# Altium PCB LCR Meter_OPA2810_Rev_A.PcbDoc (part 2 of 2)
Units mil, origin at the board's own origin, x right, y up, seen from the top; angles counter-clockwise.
Board outline 3760 x 2600 mil, 4 copper layers (L01_TOP, L02_GND, L03_PWR, L04_BOT), stack 62.234 mil thick; 153 components, 56 nets, 334 pads, 170 vias.
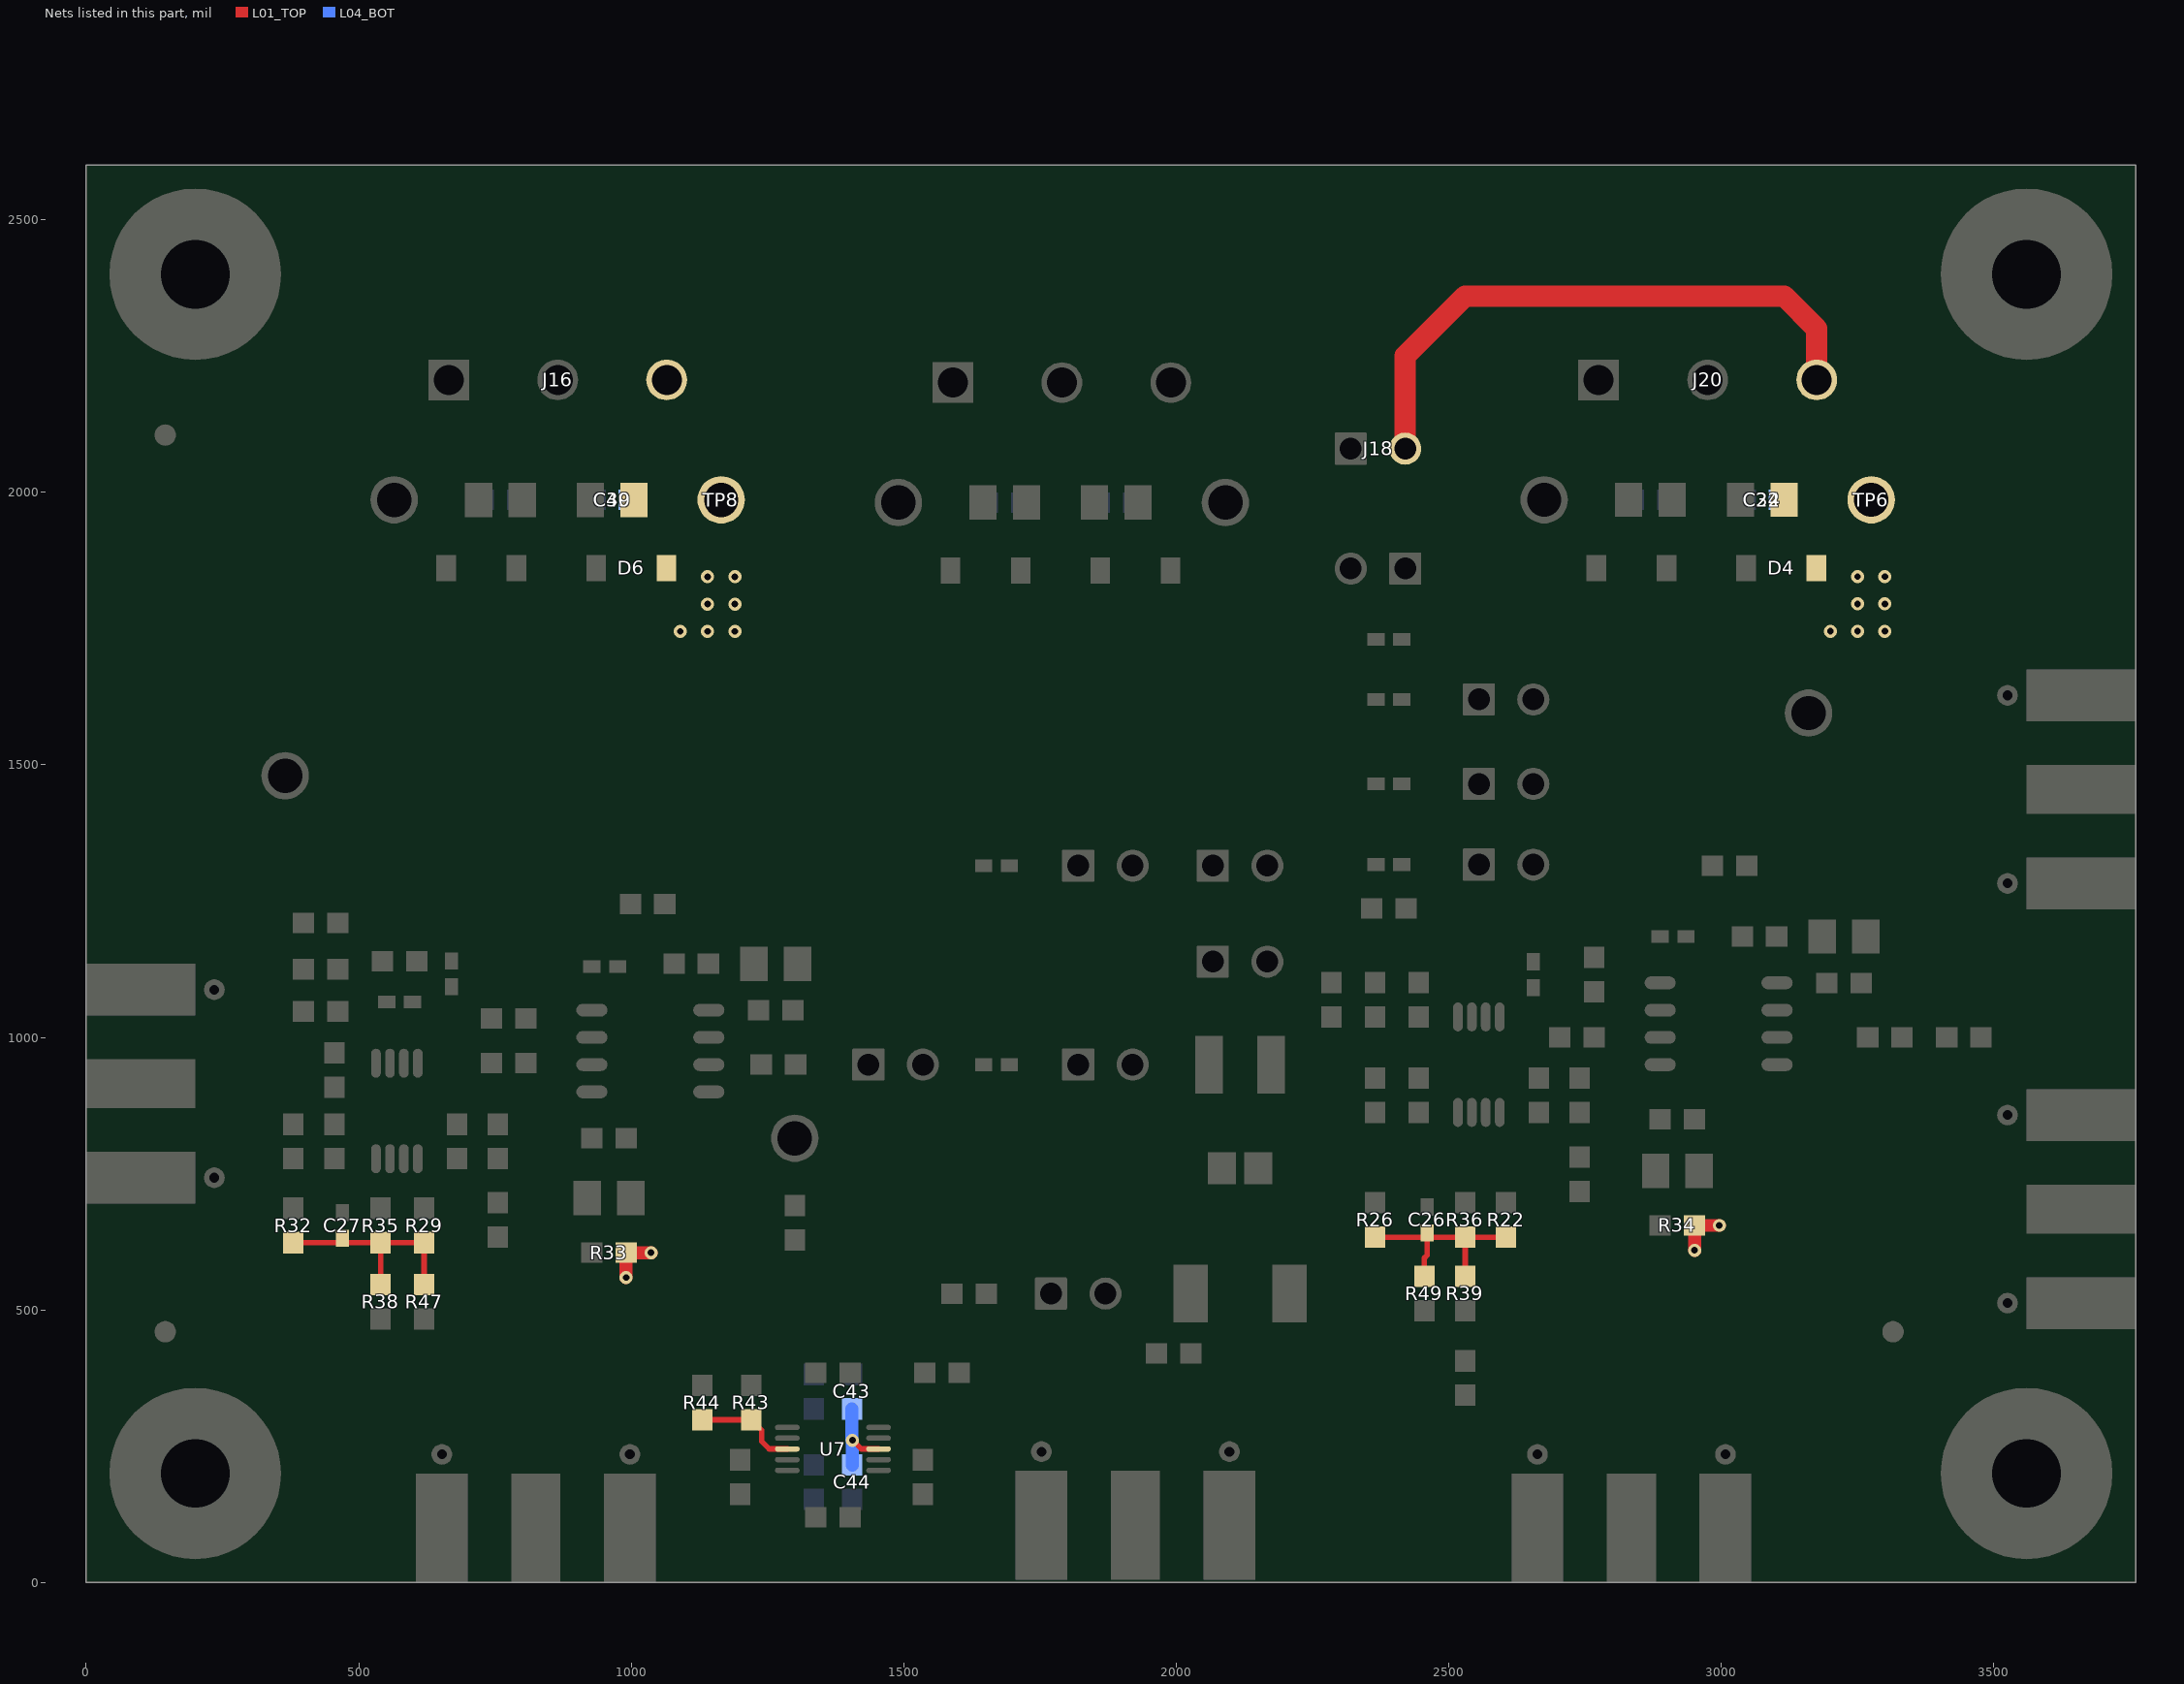
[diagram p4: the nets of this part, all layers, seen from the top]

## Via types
v1: diameter 24, hole 12, L01_TOP to L04_BOT, tented both sides, 170 vias

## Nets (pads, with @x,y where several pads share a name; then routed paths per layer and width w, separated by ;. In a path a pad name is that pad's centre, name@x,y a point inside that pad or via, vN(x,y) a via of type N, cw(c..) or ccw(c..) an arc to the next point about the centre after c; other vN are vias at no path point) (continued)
VEE2: C24.1 C32.2 D4.2 J18.2 J20.3 R33.1 R34.1 TP6.1 | length 1271.2
  L01_TOP w24: v1(990.7,559.5) R33.1@990.7,605 v1(1036.21,605) ; v1(2950.71,609.5) R34.1@2950.71,655.01 v1(2996.22,655.01)
  L01_TOP w39.3: J18.2@2420,2080 2420,2250 2530,2360 3115,2360 3175,2300 J20.3@3175,2206.21
  other v1: 3200,1745.09 3250,1745.09 3300,1745.09 3250,1795.09 3300,1795.09 3250,1845.09 3300,1845.09
VEE3: C39.1 C40.2 C43.1 C44.2 D6.2 J16.3 TP8.1 U7.8 | length 158
  L01_TOP w10: v1(1406,261) 1422,245 U7.8@1453.66,245
  L04_BOT w24: C43.1@1405,318.5 1405,262 v1(1406,261) 1405.43,260.43 C44.2@1405.43,215.47
  other v1: 1090.01,1745 1140.01,1745 1190.01,1745 1140.01,1795 1190.01,1795 1140.01,1845 1190.01,1845
VG: R43.2 R44.1 U7.3 | length 190.5
  L01_TOP w10: R44.1@1130,298.5 R43.2@1220,298.5 1239,279.5 1239,259 1253,245 U7.3@1286.34,245
VIN+: C27.1 R29.2 R32.2 R35.2 R38.1 R47.1 | length 400.5
  L01_TOP w10: R32.2@380,623.5 462.13,623.5 C27.1@470,631.38 477.87,623.5 R35.2@540,623.5 ; R38.1@540,546.5 R35.2@540,623.5 ; R47.1@620,546.5 R29.2@620,623.5 R35.2@540,623.5
VIN-: C26.1 R22.2 R26.2 R36.2 R39.1 R49.1 | length 400.5
  L01_TOP w10: R26.2@2365,633.5 2452.13,633.5 C26.1@2460,641.38 ; R49.1@2455,561.5 2455,595 2460,600 C26.1@2460,641.38 ; R39.1@2530,561.5 R36.2@2530,633.5 ; R22.2@2605,633.5 R36.2@2530,633.5 ; C26.1@2460,641.38 2467.88,633.5 R36.2@2530,633.5
pads on no net: FID1.1 FID2.1 FID3.1 H1.1 H2.1 H3.1 H4.1 H5.0 H6.0 H7.0 H8.0 LBL1.0 U3.2 U3.5 U3.8 U4.2 U4.5 U4.8

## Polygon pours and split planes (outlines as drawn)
GND on L01_TOP "L01_TOP_GND_P016" (solid, remove dead copper, pour order 16): 765,1740 780,1725 945,1725 960,1740 960,1930 950,1940 950,2250 930,2270 795,2270 775,2250 775,1940 765,1930
VCC3 on L01_TOP "L01_TOP_VCC3_P020" (solid, remove dead copper, pour order 20): 490,1755 520,1725 655,1725 685,1755 685,1885 745,1945 745,2030 735,2040 735,2250 715,2270 520,2270 490,2240
VEE3 on L01_TOP "L01_TOP_VEE3_P024" (solid, remove dead copper, pour order 24): 1045.01,1739.99 1060,1725 1225,1725 1240.01,1740.01 1240.01,2240 1210.01,2270 1015.01,2270 995.01,2250 995.01,2040 985.01,2030 985.01,1945 1045.01,1885
VEE1 on L01_TOP "L01_TOP_VEE1_P028" (solid, remove dead copper, pour order 28): 1970.01,1734.99 1985,1720 2150,1720 2165.01,1735.01 2165.01,2235 2135.01,2265 1940.01,2265 1920.01,2245 1920.01,2035 1910.01,2025 1910.01,1940 1970.01,1880
VCC1 on L01_TOP "L01_TOP_VCC1_P030" (solid, remove dead copper, pour order 30): 1415,1750 1445,1720 1580,1720 1610,1750 1610,1880 1670,1940 1670,2025 1660,2035 1660,2245 1640,2265 1445,2265 1415,2235
GND on L01_TOP "L01_TOP_GND_P032" (solid, remove dead copper, pour order 32): 1690,1735 1705,1720 1870,1720 1885,1735 1885,1925 1875,1935 1875,2245 1855,2265 1720,2265 1700,2245 1700,1935 1690,1925
VEE2 on L01_TOP "L01_TOP_VEE2_P040" (solid, remove dead copper, pour order 40): 3155,1740.08 3170,1725.09 3335,1725.09 3350,1740.1 3350,2240.09 3320,2270.09 3125,2270.09 3105,2250.09 3105,2040.09 3095,2030.09 3095,1945.09 3155,1885.09
VCC2 on L01_TOP "L01_TOP_VCC2_P042" (solid, remove dead copper, pour order 42): 2600,1755.09 2630,1725.09 2765,1725.09 2795,1755.09 2795,1885.09 2855,1945.09 2855,2030.09 2845,2040.09 2845,2250.09 2825,2270.09 2630,2270.09 2600,2240.09
GND on L01_TOP "L01_TOP_GND_P044" (solid, remove dead copper, pour order 44): 2875,1740.09 2890,1725.09 3055,1725.09 3070,1740.09 3070,1930.09 3060,1940.09 3060,2250.09 3040,2270.09 2905,2270.09 2885,2250.09 2885,1940.09 2875,1930.09
GND on L01_TOP "L01_TOP_GND_P052" (solid, remove dead copper, pour order 52): 0,2600 0,0 3760,0 3760,2600
GND on L04_BOT "L04_BOT_GND_P018" (solid, remove dead copper, pour order 18): 765,1740 780,1725 945,1725 960,1740 960,1930 950,1940 950,2250 930,2270 795,2270 775,2250 775,1940 765,1930
VCC3 on L04_BOT "L04_BOT_VCC3_P022" (solid, remove dead copper, pour order 22): 490,1755 520,1725 655,1725 685,1755 685,1885 745,1945 745,2030 735,2040 735,2250 715,2270 520,2270 490,2240
VEE3 on L04_BOT "L04_BOT_VEE3_P026" (solid, remove dead copper, pour order 26): 1045.01,1739.99 1060,1725 1225,1725 1240.01,1740.01 1240.01,2240 1210.01,2270 1015.01,2270 995.01,2250 995.01,2040 985.01,2030 985.01,1945 1045.01,1885
VEE1 on L04_BOT "L04_BOT_VEE1_P034" (solid, remove dead copper, pour order 34): 1970.01,1734.99 1985,1720 2150,1720 2165.01,1735.01 2165.01,2235 2135.01,2265 1940.01,2265 1920.01,2245 1920.01,2035 1910.01,2025 1910.01,1940 1970.01,1880
VCC1 on L04_BOT "L04_BOT_VCC1_P036" (solid, remove dead copper, pour order 36): 1415,1750 1445,1720 1580,1720 1610,1750 1610,1880 1670,1940 1670,2025 1660,2035 1660,2245 1640,2265 1445,2265 1415,2235
GND on L04_BOT "L04_BOT_GND_P038" (solid, remove dead copper, pour order 38): 1690,1735 1705,1720 1870,1720 1885,1735 1885,1925 1875,1935 1875,2245 1855,2265 1720,2265 1700,2245 1700,1935 1690,1925
VEE2 on L04_BOT "L04_BOT_VEE2_P046" (solid, remove dead copper, pour order 46): 3155,1740.08 3170,1725.09 3335,1725.09 3350,1740.1 3350,2240.09 3320,2270.09 3125,2270.09 3105,2250.09 3105,2040.09 3095,2030.09 3095,1945.09 3155,1885.09
VCC2 on L04_BOT "L04_BOT_VCC2_P048" (solid, remove dead copper, pour order 48): 2600,1755.09 2630,1725.09 2765,1725.09 2795,1755.09 2795,1885.09 2855,1945.09 2855,2030.09 2845,2040.09 2845,2250.09 2825,2270.09 2630,2270.09 2600,2240.09
GND on L04_BOT "L04_BOT_GND_P050" (solid, remove dead copper, pour order 50): 2875,1740.09 2890,1725.09 3055,1725.09 3070,1740.09 3070,1930.09 3060,1940.09 3060,2250.09 3040,2270.09 2905,2270.09 2885,2250.09 2885,1940.09 2875,1930.09
GND on L04_BOT "L04_BOT_GND_P054" (solid, remove dead copper, pour order 54): 0,2600 0,0 3760,0 3760,2600
GND on L02_GND (split plane): 3739.9,20.1 20.1,20.1 20.1,2579.9 3739.9,2579.9
VCC2 on L03_PWR (split plane): 3083.44,1029.56 2867.56,1029.56 2867.56,1287 3007,1287 3007,1342 3006,1343 2867.56,1343 2867.56,1689 2867.32,1691.45 2866.6,1693.81 2865.44,1695.98 2863.88,1697.88 2861.98,1699.44 2859.81,1700.6 2857.45,1701.32 2855,1701.56 2607.56,1701.56 2607.56,2370 2607.32,2372.45 2606.6,2374.81 2605.44,2376.98 2603.88,2378.88 2601.98,2380.44 2599.81,2381.6 2597.45,2382.32 2595,2382.56 1412,2382.56 1409.55,2382.32 1407.19,2381.6 1405.02,2380.44 1403.12,2378.88 1401.56,2376.98 1400.4,2374.81 1399.68,2372.45 1399.44,2370 1399.44,1095.56 973.56,1095.56 973.56,1173.44 1045,1173.44 1047.45,1173.68 1049.81,1174.4 1051.98,1175.56 1053.88,1177.12 1055.44,1179.02 1056.6,1181.19 1057.32,1183.55 1057.56,1186 1057.56,1362.44 1257,1362.44 1259.45,1362.68 1261.81,1363.4 1263.98,1364.56 1265.88,1366.12 1267.44,1368.02 1268.6,1370.19 1269.32,1372.55 1269.56,1375 1269.56,2579.9 3083.44,2579.9
GND on L03_PWR (split plane): 2292,901 2312.44,901 2312.44,724.98 2208.2,724.98 2208.2,933 2260,933
VEE2 on L03_PWR (split plane): 3739.9,20.1 1609.56,20.1 1609.56,563 1609.32,565.45 1608.6,567.81 1607.44,569.98 1605.88,571.88 1603.98,573.44 1601.81,574.6 1599.45,575.32 1597,575.56 1175.02,575.56 1172.57,575.32 1170.21,574.6 1168.04,573.44 1166.14,571.88 1019.82,425.56 955.56,425.56 955.56,670.44 1960.44,670.44 1960.44,229 1960.68,226.55 1961.4,224.19 1962.56,222.02 1964.12,220.12 1966.02,218.56 1968.19,217.4 1970.55,216.68 1973,216.44 2855,216.44 2857.45,216.68 2859.81,217.4 2861.98,218.56 2863.88,220.12 2865.44,222.02 2866.6,224.19 2867.32,226.55 2867.56,229 2867.56,980 2918,980 2924,986 2924,1004.44 3067,1004.44 3067,988 3075.01,979.99 3249,979.99 3260,968.99 3294.01,968.99 3294.01,1028.99 3264,1028.99 3255,1019.99 3108.56,1019.99 3108.56,2579.9 3739.9,2579.9
VCC1 on L03_PWR (split plane): 179 vertices, not listed, extent 594.56,241.56 2842.44,2357.44
VEE1 on L03_PWR (split plane): 2312.44,1337.48 2279.49,1337.48 2279.49,1300.51 2280,1300 2312.44,1300 2312.44,944 2301,944 2274,971 2208.2,971 2208.2,1299.8 2259,1299.98 2259,1337.48 2216.98,1337.48 2216.98,1364.98 2125,1364.98 2125,594.96 2164.99,594.96 2164.99,465.04 2251.6,465.04 2251.6,674 2312.44,674 2312.44,241.56 1985.56,241.56 1985.56,683 1985.32,685.45 1984.6,687.81 1983.44,689.98 1981.88,691.88 1979.98,693.44 1977.81,694.6 1975.45,695.32 1973,695.56 943,695.56 940.55,695.32 938.19,694.6 936.02,693.44 934.12,691.88 932.56,689.98 931.4,687.81 930.68,685.45 930.44,683 930.44,425.56 566.2,425.56 309.56,682.2 309.56,866 309.56,1362.44 569.44,1362.44 569.44,1166 516,1166 516,1040 569.44,986.56 569.44,984 511,984 511,745 546,745 546,715 450,715 450,658 568,658 568,745 569.44,745 569.44,565 569.68,562.55 570.4,560.19 571.56,558.02 573.12,556.12 575.02,554.56 577.19,553.4 579.55,552.68 582,552.44 807,552.44 809.45,552.68 811.81,553.4 813.98,554.56 815.88,556.12 817.44,558.02 818.6,560.19 819.32,562.55 819.56,565 819.56,816.44 1784,816.44 1786.45,816.68 1788.81,817.4 1790.98,818.56 1792.88,820.12 1794.44,822.02 1795.6,824.19 1796.32,826.55 1796.56,829 1796.56,1965.44 2312.44,1965.44
VEE3 on L03_PWR (split plane): 1244.44,1387.56 297,1387.56 294.55,1387.32 292.19,1386.6 290.02,1385.44 288.12,1383.88 286.56,1381.98 285.4,1379.81 284.68,1377.45 284.44,1375 284.44,866 284.44,677 284.68,674.55 285.4,672.19 286.56,670.02 288.12,668.12 552.12,404.12 554.02,402.56 556.19,401.4 558.55,400.68 561,400.44 1025.02,400.44 1027.47,400.68 1029.82,401.4 1032,402.56 1033.9,404.12 1180.22,550.44 1584.44,550.44 1584.44,20.1 1366.56,20.1 1366.56,408 1366.32,410.45 1365.6,412.81 1364.44,414.98 1362.88,416.88 1360.98,418.44 1358.81,419.6 1356.45,420.32 1354,420.56 1184,420.56 1181.55,420.32 1179.19,419.6 1177.02,418.44 1175.12,416.88 1173.56,414.98 1172.4,412.81 1171.68,410.45 1171.44,408 1171.44,234.56 320.56,234.56 320.56,327 320.32,329.45 319.6,331.81 318.44,333.98 316.88,335.88 314.98,337.44 312.81,338.6 310.45,339.32 308,339.56 151.56,339.56 151.56,1606.44 867,1606.44 869.45,1606.68 871.81,1607.4 873.98,1608.56 875.88,1610.12 877.44,1612.02 878.6,1614.19 879.32,1616.55 879.56,1619 879.56,2579.9 1244.44,2579.9
VCC3 on L03_PWR (split plane): 854.44,1631.56 139,1631.56 136.55,1631.32 134.19,1630.6 132.02,1629.44 130.12,1627.88 128.56,1625.98 127.4,1623.81 126.68,1621.45 126.44,1619 126.44,327 126.68,324.55 127.4,322.19 128.56,320.02 130.12,318.12 132.02,316.56 134.19,315.4 136.55,314.68 139,314.44 295.44,314.44 295.44,222 295.68,219.55 296.4,217.19 297.56,215.02 299.12,213.12 301.02,211.56 303.19,210.4 305.55,209.68 308,209.44 1184,209.44 1186.45,209.68 1188.81,210.4 1190.98,211.56 1192.88,213.12 1194.44,215.02 1195.6,217.19 1196.32,219.55 1196.56,222 1196.56,395.44 1310.02,395.44 1310.02,377.02 1274,341 1274,293 1259,293 1259,277 1312,277 1312,295 1300,295 1300,327 1330,357 1341.44,357 1341.44,208.56 1337,213 1259,213 1259,198 1310,198 1327,181 1327,146 1310,146 1310,93 1341.44,93 1341.44,20.1 20.1,20.1 20.1,2579.9 854.44,2579.9

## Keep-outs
Keep-Out Layer:
  text ".Layer_Name" at 577,-858.49 h60

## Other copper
L01_TOP:
  text ".Layer_Name" at 577,-858.49 h60
L04_BOT:
  text ".Layer_Name" at 577,-858.49 h60
L02_GND (plane layer: these items are gaps in the copper):
  region: 2125,594.96 2164.99,594.96 2164.99,465.04 2251.6,465.04 2251.6,674 2392.27,674 2392.27,724.98 2208.2,724.98 2208.2,933 2260,933 2292,901 2388,901 2392.27,905.27 2392.27,927.9 2418.25,953.88 2496,953.88 2496,830 2614,830 2614,1024 2656,1024 2674,1006 2674,973 2727,973 2727,1020 2692,1055 2692,1068 2726,1102 2726,1210 2803,1287 3007,1287 3007,1342 3006,1343 2799,1343 2692,1236 2692,1120 2682,1110 2634,1110 2634,1052 2614,1052 2614,1069 2608,1069 2608,1071 2583,1071 2583,1069 2578,1069 2578,1071 2557,1071 2557,1069 2496,1069 2496,985 2398,985 2375,962 2344,962 2326,944 2301,944 2274,971 2208.2,971 2208.2,1299.8 2208,1300 2321,1300 2321,1202 2381,1202 2381,1760 2342,1760 2342,1337.48 2216.98,1337.48 2216.98,1364.98 2125,1364.98
  region: 880,1217 1022,1217 1022,1273 861,1273 701,1113 648,1113 648,1060 599,1011 594,1011 570,1035 570,1166 516,1166 516,1040 572,984 511,984 511,745 546,745 546,715 450,715 450,658 568,658 568,745 572,745 572,658 647.27,658 647.27,715 594,715 594,745 629,745 629,921 766,921 766,980 629,980 629,984 625,984 625,989 710,1074 737,1074
  region: 783,921 836,921 845,930 958,930 964,936 964,961 955,970 851,970 840,981 840,1064 836,1068 783,1068
  region: 1379,357 1483,357 1483,277 1478,272 1427,272 1427,257 1497,257 1510,270 1510,358 1562,358 1562,412 1379,412
  region: 1312,277 1259,277 1259,293 1274,293 1274,341 1310.02,377.02 1310.02,412.2 1360.05,412.2 1362.27,409.98 1362.27,357.73 1363,357 1330,357 1300,327 1300,295 1312,295
  region: 1259,213 1337,213 1361,189 1361,93 1310,93 1310,146 1327,146 1327,181 1310,198 1259,198
  region: 1481,213 1403,213 1379,189 1379,93 1430,93 1430,146 1413,146 1413,181 1430,198 1481,198
  region: 1229.99,918.99 1264,918.99 1264,978.99 1233.99,978.99 1224.99,969.99 1111.99,969.99 1105.99,963.99 1105.99,938.99 1114.99,929.99 1218.99,929.99
  region: 2739,971 2796,971 2805,980 2918,980 2924,986 2924,1011 2915,1020 2811,1020 2794,1037.01 2794,1118 2739,1118
  region: 3074.99,1019.99 3067,1012 3067,988 3075.01,979.99 3249,979.99 3260,968.99 3294.01,968.99 3294.01,1028.99 3264,1028.99 3255,1019.99
  text ".Layer_Name" at 577,-858.49 h60
L03_PWR (plane layer: these items are gaps in the copper):
  region: 2557,782.5 2578,761.5 2578,672 2632.27,672 2632.27,756.73 2579,810 2579,830 2614,830 2614,1024 2656,1024 2674,1006 2674,973 2727,973 2727,1020 2692,1055 2692,1068 2726,1102 2726,1210 2803,1287 3007,1287 3007,1342 3006,1343 2799,1343 2692,1236 2692,1120 2682,1110 2634,1110 2634,1052 2614,1052 2614,1069 2608,1069 2608,1071 2583,1071 2583,1069 2578,1069 2578,1071 2557,1071 2557,1069 2496,1069 2496,985 2456,985 2456,953.88 2496,953.88 2496,830 2531,830 2531,804 2502,775 2502,715 2439,715 2439,670 2553,670 2553,830 2557,830
  region: 880,1217 1022,1217 1022,1273 861,1273 701,1113 648,1113 648,1060 599,1011 594,1011 570,1035 570,1166 516,1166 516,1040 572,984 511,984 511,745 546,745 546,715 450,715 450,658 568,658 568,745 572,745 572,658 647.27,658 647.27,715 594,715 594,745 629,745 629,921 766,921 766,980 629,980 629,984 625,984 625,989 710,1074 737,1074
  region: 783,921 836,921 845,930 958,930 964,936 964,961 955,970 851,970 840,981 840,1064 836,1068 783,1068
  region: 1229.99,918.99 1264,918.99 1264,978.99 1233.99,978.99 1224.99,969.99 1111.99,969.99 1105.99,963.99 1105.99,938.99 1114.99,929.99 1218.99,929.99
  region: 1312,277 1259,277 1259,293 1274,293 1274,341 1310.02,377.02 1310.02,412.2 1360.05,412.2 1362.27,409.98 1362.27,357.73 1363,357 1330,357 1300,327 1300,295 1312,295
  region: 1379,357 1483,357 1483,277 1478,272 1427,272 1427,257 1497,257 1510,270 1510,358 1562,358 1562,412 1379,412
  region: 1259,213 1337,213 1361,189 1361,93 1310,93 1310,146 1327,146 1327,181 1310,198 1259,198
  region: 1481,213 1403,213 1379,189 1379,93 1430,93 1430,146 1413,146 1413,181 1430,198 1481,198
  region: 2432,953.88 2432,985 2398,985 2375,962 2344,962 2326,944 2301,944 2274,971 2208.2,971 2208.2,1299.8 2259,1299.98 2259,1337.48 2216.98,1337.48 2216.98,1364.98 2125,1364.98 2125,594.96 2164.99,594.96 2164.99,465.04 2251.6,465.04 2251.6,674 2392.27,674 2392.27,724.98 2208.2,724.98 2208.2,933 2260,933 2292,901 2388,901 2392.27,905.27 2392.27,927.9 2418.25,953.88
  region: 2739,971 2796,971 2805,980 2918,980 2924,986 2924,1011 2915,1020 2811,1020 2794,1037.01 2794,1118 2739,1118
  region: 3074.99,1019.99 3067,1012 3067,988 3075.01,979.99 3249,979.99 3260,968.99 3294.01,968.99 3294.01,1028.99 3264,1028.99 3255,1019.99
  region: 2279.49,1337.48 2279.49,1300.51 2280,1300 2321,1300 2321,1202 2381,1202 2381,1760 2336.12,1760 2336.12,1337.48
  lines w25: 582,1375 582,565 807,565 807,829 1784,829 1784,1978 2325,1978 2325,229 2324,229 ; 867,2780 867,1619 139,1619 139,327 308,327 308,222 1184,222 1184,408 1354,408 1354,-70 ; 943,413 943,683 1973,683 1973,229 2855,229 2855,1017 ; 1045,1375 1045,1186 961,1186 961,1083 1412,1083 1412,2370 2595,2370 2595,1689 2855,1689 2855,1017 ; 1257,2784 1257,1375 297,1375 297,866 297,677 561,413 1025.02,413 1175.02,563 1597,563 1597,-67 ; 3096,2681 3096,1017 2855,1017
  text ".Layer_Name" at 577,-858.49 h60
Multi-Layer:
  pour cut-out: 511,984 629,984 629,745 511,745
  pour cut-out: 2496,1069 2614,1069 2614,830 2496,830
  pour cut-out: 511,984 629,984 629,745 511,745
  pour cut-out: 572,921 572,984 516,1040 516,1166 570,1166 570,1035 594,1011 594,921
  pour cut-out: 766,921 766,980 628,980 625,983 625,989 710,1074 737,1074 880,1217 1022,1217 1022,1273 861,1273 701,1113 648,1113 648,1060 598,1010 598,921
  pour cut-out: 783,921 836,921 845,930 958,930 964,936 964,961 955,970 851,970 840,981 840,1064 836,1068 783,1068
  pour cut-out: 1229.99,918.99 1264,918.99 1264,978.99 1233.99,978.99 1224.99,969.99 1111.99,969.99 1105.99,963.99 1105.99,938.99 1114.99,929.99 1218.99,929.99
  pour cut-out: 568,808 568,658 450,658 450,715 546,715 546,808
  pour cut-out: 572,808 572,658 647.27,658 647.27,715 594,715 594,808
  pour cut-out: 2557,1071 2557,1005 2537,985 2398,985 2375,962 2344,962 2326,944 2301,944 2274,971 2208.2,971 2208.2,1299.8 2208,1300 2321,1300 2321,1202 2381,1202 2381,1760 2342,1760 2342,1337.48 2216.98,1337.48 2216.98,1364.98 2125,1364.98 2125,594.96 2164.99,594.96 2164.99,465.04 2251.6,465.04 2251.6,674 2392.27,674 2392.27,724.98 2208.2,724.98 2208.2,933 2260,933 2292,901 2388,901 2392.27,905.27 2392.27,927.9 2418.25,953.88 2546.88,953.88 2578,985 2578,1071
  pour cut-out: 2583,1071 2583,1006 2608,1006 2608,1024 2656,1024 2674,1006 2674,973 2727,973 2727,1020 2692,1055 2692,1068 2726,1102 2726,1210 2803,1287 3007,1287 3007,1342 3006,1343 2799,1343 2692,1236 2692,1120 2682,1110 2634,1110 2634,1052 2608,1052 2608,1071
  pour cut-out: 2739,971 2796,971 2805,980 2918,980 2924,986 2924,1011 2915,1020 2811,1020 2794,1037.01 2794,1118 2739,1118
  pour cut-out: 3074.99,1019.99 3067,1012 3067,988 3075.01,979.99 3249,979.99 3260,968.99 3294.01,968.99 3294.01,1028.99 3264,1028.99 3255,1019.99
  pour cut-out: 2579,810 2632.27,756.73 2632.27,672 2578,672 2578,761.5 2557,782.5 2557,893 2579,893
  pour cut-out: 2502,715 2502,775 2531,804 2531,893 2553,893 2553,670 2439,670 2439,715
  pour cut-out: 1312,277 1259,277 1259,293 1274,293 1274,341 1310.02,377.02 1310.02,412.2 1360.05,412.2 1362.27,409.98 1362.27,357.73 1363,357 1330,357 1300,327 1300,295 1312,295
  pour cut-out: 1379,357 1483,357 1483,277 1478,272 1427,272 1427,257 1497,257 1510,270 1510,358 1562,358 1562,412 1379,412
  pour cut-out: 1481,213 1403,213 1379,189 1379,93 1430,93 1430,146 1413,146 1413,181 1430,198 1481,198
  pour cut-out: 1259,213 1337,213 1361,189 1361,93 1310,93 1310,146 1327,146 1327,181 1310,198 1259,198

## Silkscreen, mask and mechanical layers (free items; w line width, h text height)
Top Overlay:
  region: 1485,2375 1185,2375 1185,2275 1485,2275
  lines w7: 385,895 400,895 420,875 ; 430,585 430,595 440,605 ; 488,561 488,578 502,592 ; 520,1180 520,1240 530,1250
  text "VEE3" at 1295,1905 h72.83 r90
  text "VEE1" at 2225,1905 h72.83 r90
  text "VEE2" at 3420,1905 h72.83 r90
  text "VCC1" at 1405,1900 h72.83 r90
  text "VCC3" at 480,1895 h72.83 r90
  text "VCC2" at 2585,1895 h72.83 r90
  text "NOV 2018" at 3650,1805 h72.83 r90
  text "4 LAYER" at 3720,1805 h72.83 r90
  text "GND" at 3085,1465 h72.83
  text "GND" at 285,1345 h72.83
  text "V1_OUT" at 3460,1220 h72.83 r90
  text "IN_TP" at 1355,705 h72.83
  text "INPUT" at 75,605 h72.83
  text "V2_OUT" at 3210,595 h72.83
  text "'.PRJ_Number'.PCB_Rev" at 2590,340 h80
  text "V3_OUT" at 715,310 h72.83
  text "VCA_OUT" at 1840,305 h72.83
  text "V4_OUT" at 2330,175 h72.83
  text ".Layer_Name" at 577,-858.49 h60
Bottom Overlay:
  text ".Layer_Name" at 577,-858.49 h60
Top Paste:
  text ".Layer_Name" at 577,-858.49 h60
Bottom Paste:
  text ".Layer_Name" at 577,-858.49 h60
Top Solder:
  text ".Layer_Name" at 577,-858.49 h60
  text ".Layer_Name" at 577,-858.49 h60
Bottom Solder:
  text ".Layer_Name" at 577,-858.49 h60
Drill Guide:
  text ".Layer_Name" at 577,-858.49 h60
M1 Board Outline:
  the board outline again, w10
  text ".Layer_Name" at 2870,-130 h60
M2 Board Dimensions:
  rectangle: 125,-400 500,-275
  rectangle: 0,-275 125,-150
  lines w7: 0,-275 1000,-275 ; 125,-400 125,-150 ; 250,-400 250,-150 ; 500,-400 500,-150 ; 750,-400 750,-150 ; 0,-400 0,-150 1000,-150 1000,-400 0,-400
  text ".Layer_Name" at 577,-858.49 h60
M3 3D STEP Top:
  text ".Layer_Name" at 577,-858.49 h60
M4 3D STEP Bottom:
  text ".Layer_Name" at 577,-858.49 h60
M5 Assembly Top:
  lines w10: -292,-930.17 6308,-930.17 ; -292,-726.83 6310,-726.83 ; -292,-523.5 -292,-1133.5 3713,-1133.5 6310,-1133.5 6310,-523.5 -291.5,-523.5 -291.5,-1133.5 1284,-1133.5 ; 2173,-1133.5 2173,-523.5 ; 3440,-726.83 3440,-523.5 ; 4280,-726.83 4280,-523.5 ; 4902,-1140 4902,-937.17
  text "COMPONENTS MARKED 'DNP' SHOULD NOT BE POPULATED." at 1153.5,-318.5 h60
  text "ASSEMBLY VARIANT:" at 1153,-434 h60
  text ".VariantName" at 2189,-434 h60
  text "PCB VIEWED FROM TOP SIDE" at -228.5,-655.67 h60
  text "BOARD #:" at 2248,-655.67 h60
  text ".PRJ_Number" at 2793.5,-655.67 h60
  text "REV:" at 3638,-655.67 h60
  text ".PCB_Rev" at 3929.5,-655.67 h60
  text "SVN REV:" at 4476,-655.67 h60
  text ".VersionControl_RevNumber" at 4982,-655.67 h60
  text "TID #:" at 2248,-859 h60
  text ".TID" at 2793.5,-859 h60
  text "PLOT NAME =" at -228.5,-1064.34 h60
  text ".plot_File_Name" at 577,-1064.34 h60
  text "GENERATED    :" at 2250,-1064.34 h60
  text ".Print_Date" at 3119.5,-1064.34 h60
  text ".Print_Time" at 3848.5,-1064.34 h60
  text "TEXAS INSTRUMENTS" at 5113,-1064.34 h60
M6 Assembly Bottom:
  lines w10: -292.5,-727.33 6309.5,-727.33 ; -290.5,-930.67 6309.5,-930.67 ; 1115.5,-1140.5 1115.5,-937.67 ; 1737.5,-727.33 1737.5,-524 ; 2577.5,-727.33 2577.5,-524 ; 3844.5,-1134 3844.5,-524 ; 4733.5,-1134 6309,-1134 6309,-524 -292.5,-524 -292.5,-1134 2304.5,-1134 6309.5,-1134 6309.5,-524
  text "COMPONENTS MARKED 'DNP' SHOULD NOT BE POPULATED." at 6102,-318 h60
  text ".VariantName" at 5058,-434 h60
  text "ASSEMBLY VARIANT:" at 6097,-434 h60
  text ".VersionControl_RevNumber" at 1035.5,-656.17 h60
  text "SVN REV:" at 1541.5,-656.17 h60
  text ".PCB_Rev" at 2088,-656.17 h60
  text "REV:" at 2379.5,-656.17 h60
  text ".PRJ_Number" at 3224,-656.17 h60
  text "BOARD #:" at 3769.5,-656.17 h60
  text "PCB VIEWED FROM BOTTOM SIDE" at 6246,-656.17 h60
  text ".TID" at 3224,-859.5 h60
  text "TID #:" at 3769.5,-859.5 h60
  text "TEXAS INSTRUMENTS" at 904.5,-1064.84 h60
  text ".Print_Time" at 2169,-1064.84 h60
  text ".Print_Date" at 2898,-1064.84 h60
  text "GENERATED    :" at 3767.5,-1064.84 h60
  text ".plot_File_Name" at 5440.5,-1064.84 h60
  text "PLOT NAME =" at 6246,-1064.84 h60
M9 Title Sheet:
  drawing of 57 lines, arcs and shapes, not listed
  text "1" at 739.84,8036.5 h70
  text "2" at 3235.5,8036.5 h70
  text "3" at 5724.84,8036.5 h70
  text "4" at 8231.51,8036.5 h70
  text "5" at 10730.5,8036.5 h70
  text "6" at 13235.5,8036.5 h70
  text "A" at -416.5,6893.5 h70
  text "A" at 14383.5,6893.5 h70
  text "B" at -416.5,4513.5 h70
  text "B" at 14383.5,4513.5 h70
  text "C" at -416.5,2138.5 h70
  text "C" at 14383.5,2138.5 h70
  text "PROJECT TITLE:" at 11343.5,277.5 h45
  text ".PRJ_Title" at 11393.5,144.17 h70
  text "DESIGNED FOR:" at 11343.5,-23.5 h45
  text ".PRJ_Customer" at 11393.5,-163.5 h70
  text "D" at -416.5,-231.5 h70
  text "D" at 14383.5,-231.5 h70
  text "FILE NAME:" at 11343.5,-323.5 h45
  text ".PCB_File_Name_No_Path" at 11393.5,-443.5 h70
  text "Texas Instruments (TI) and/or its licensors do not warrant the accuracy or completeness of this specification" at 6374,-605.34 h45
  text "ENGINEER:" at 11343.5,-613.5 h45
  text "LAYOUT BY:" at 12848.5,-613.5 h45
  text "or any information contained therein. TI and/or its licensors do not warrant that this design will meet" at 6329.01,-718 h45
  text ".PRJ_Engineer" at 11393.5,-768.49 h70
  text ".PCB_Layout" at 12899,-768.49 h70
  text "the specifications, will be suitable for your application or fit for any particular purpose, or will operate in" at 6329.01,-830.67 h45
  text ".Layer_Name" at 577,-858.49 h60
  text "ALTIUM DESIGNER VERSION:" at 12848.5,-923.5 h45
  text "an implementation. TI and/or its licensors do not warrant that the design is production worthy. You should" at 6329.01,-943.33 h45
  text "completely validate and test your design implementation to confirm the system functionality for your application." at 6374,-1056 h45
  text ".print_Scale" at 11393.5,-1056.83 h70
  text ".Application_BuildNumber" at 12899,-1056.83 h70
  text "1" at 739.84,-1263.5 h70
  text "2" at 3235.5,-1263.5 h70
  text "3" at 5724.84,-1263.5 h70
  text "4" at 8231.51,-1263.5 h70
  text "5" at 10730.5,-1263.5 h70
  text "6" at 13235.5,-1263.5 h70
M10 Fab Notes:
  drawing of 190 lines, arcs and shapes, not listed
  text "DESIGN INFORMATION" at 12382.02,6356.17 h60
  text "MIN. TRACK WIDTH:" at 11737.46,6224.05 h60
  text "8" at 12833.7,6224.05 h60
  text "MIL" at 12988.46,6224.05 h60
  text "MIN. CLEARANCE:" at 11737.46,6099.92 h60
  text "0.2" at 12773.7,6099.93 h60
  text "mm" at 12988.46,6099.92 h60
  text "MIN. VIA PAD SIZE:" at 11737.46,5975.8 h60
  text "24" at 12803.71,5975.8 h60
  text "MIL" at 12988.46,5975.8 h60
  text "0.05mm (2MIL)" at 12432.46,5845.9 h60
  text "MINIMUM ANNULAR RING" at 11408.23,5837.67 h60
  text "EXTERNAL" at 13140.46,5837.67 h60
  text "PER" at 11608.23,5727.55 h60
  text "IPC-D-275 CLASS 2 LEVEL C" at 11828.23,5727.54 h60
  text "MIL, HOLES" at 13316.46,5627.07 h60
  text "+/-" at 12924,5618.48 h60
  text "+/-" at 13778,5618.48 h60
  text "REGISTRATION TOLERANCES:" at 11408.23,5617.42 h60
  text "METAL" at 12608,5617.42 h60
  text "5" at 13184.2,5617.42 h60
  text "3" at 14017.2,5617.42 h60
  text "MIL" at 14133.46,5617.42 h60
  text "HOLE SIZE TOLERANCE (UNLESS OTHERWISE SPECIFIED):" at 11408.23,5519.1 h60
  text "+/-" at 13778,5516.23 h60
  text "3" at 14017.2,5515.17 h60
  text "MIL" at 14133.46,5515.17 h60
  text "MATERIAL:" at 11333.46,5377.52 h60
  text "FR-4 High Tg" at 12319.9,5249 h60
  text "X" at 12175.46,5241.01 h60
  text "FR-408" at 11754.46,5236.49 h60
  text "OTHER" at 13242.46,5236.49 h60
  text "62 MIL (1.6mm) +/-10%" at 12074.56,5093.46 h60
  text "X" at 11954.46,5091.01 h60
  text "THICKNESS:" at 11408.23,5085.24 h60
  text "OTHER" at 13359.46,5085.24 h60
  text "TOLERANCE:" at 11408.23,4946.92 h60
  text "X" at 12256.46,4946.92 h60
  text "ANSI IPC-6012 TYPE 3 CLASS 2" at 12434.48,4946.92 h60
  text "OTHER +/-" at 12434.46,4802.73 h60
  text "BOW & TWIST:" at 11408.23,4657.54 h60
  text "X" at 12256.46,4657.54 h60
  text "ANSI IPC-6012 TYPE 3 CLASS 2" at 12434.48,4657.54 h60
  text "OTHER +/-" at 12434.46,4510.85 h60
  text "DRILLING:" at 11333.46,4380.23 h60
  text "NC_DRILL FILES" at 13094.46,4275.04 h60
  text "REFERENCE:" at 11408.23,4271.1 h60
  text "X" at 12065.46,4271.01 h60
  text "AS SHOWN" at 12243.46,4271.1 h60
  text "X" at 12966.46,4271.1 h60
  text "OTHER" at 13392.46,4128.85 h60
  text "PTH COPPER THICKNESS:" at 11407.91,4125.32 h60
  text "X" at 12547.14,4125.32 h60
  text "20-30 um" at 12675.14,4125.32 h60
  text "BOARD FINISH:" at 11333.46,3977.73 h60
  text "SILKSCREEN:" at 11488.68,3867.6 h60
  text "X" at 12446.46,3867.6 h60
  text "TOP" at 12563.46,3867.6 h60
  text "X" at 12956.46,3867.6 h60
  text "BOTTOM" at 13074.46,3867.6 h60
  text "SILKSCREEN COLOR:" at 11488.68,3712.41 h60
  text "X" at 12445.46,3712.41 h60
  text "WHITE" at 12563.46,3712.41 h60
  text "OTHER" at 13074.46,3712.41 h60
  text "X" at 12576.46,3568.96 h60
  text "GREEN" at 12694.46,3568.96 h60
  text "OTHER" at 13312.46,3568.96 h60
  text "SOLDER RESIST COLOR:" at 11488.68,3562.1 h60
  text "X" at 12576.46,3414.71 h60
  text "MATTE" at 12694.46,3414.71 h60
  text "SEMI-GLOSS" at 13312,3414.07 h60
  text "IMMERSION GOLD (ENIG)" at 12394.46,3241.94 h60
  text "ENEPIG" at 13732,3234.72 h60
  text "SURFACE FINISH:" at 11333.46,3233.72 h60
  text "X" at 12216.46,3233.72 h60
  text "IMM. TIN/SILVER OR EQUIV" at 11663,3096.4 h60
  text "OTHER" at 13094.46,3092.47 h60
  text "ARRAY/PANEL:" at 11333.46,2937.09 h60
  text "X" at 12210,2930 h60
  text "CUT AND TRIM PER M1 BOARD OUTLINE" at 12394.46,2928.87 h60
  text "FAB NOTES:" at 4383.23,2826.92 h60
  text "N.C. ROUTE" at 12394.46,2792.9 h60
  text "V. SCORE" at 13260.46,2792.9 h60
  text "1) 10mils on L01_TOP and L04_BOT should be 50 Ohms impedance controlled" at 4345,2670 h60
  text "CERTIFICATION:" at 11333.46,2663.77 h60
  text "MATERIALS AND WORKMANSHIP FOR ALL PCBS" at 12058.46,2663.77 h60
  text "TO MEET OR EXCEED THE REQUIREMENTS OF:" at 12058.46,2569.71 h60
  text "2) L02_GND and L03_PWR are Negative layers is used in the design" at 4335,2525 h60
  text "X" at 11695.97,2441.08 h60
  text "ANSI IPC-A-600F CLASS ->" at 11823.96,2441.08 h60
  text "X" at 13471.97,2441.08 h60
  text "2" at 13581.96,2441.08 h60
  text "1" at 13266.96,2439.58 h60
  text "3" at 13935.96,2439.58 h60
  text "3) Dielectric thickness shown in the stackup can be adjusted to achieve the impedance control" at 4345,2370 h60
  text "X" at 12507.97,2293.39 h60
  text "RoHS" at 12635.96,2293.39 h60
  text "OTHER" at 13280.36,2293.39 h60
  text "PER ORDER" at 13677.42,2293.39 h60
  text "4) UL logo is not mandatory, can be ignored if not available" at 4340,2225 h60
  text "ALL BOARDS MUST MEET OR EXCEED UL94-V0 REQUIREMENTS." at 11361,2139.57 h60
  text "PCB MUST BEAR THE UL94V-0 UL REGISTERED MATERIAL ID NUMBER" at 11361,2023.5 h60
  text "ADDITIONAL REQUIREMENTS:" at 11333.46,1854.08 h60
  text "MICROSECTION:" at 11408.23,1746.95 h60
  text "YES" at 12313.96,1746.95 h60
  text "REQUIRED" at 13175.46,1602.62 h60
  text "BARE BOARD ELEC. TEST:" at 11408.23,1599.76 h60
  text "NONE" at 12713.96,1599.76 h60
  text "X" at 13057.46,1599.76 h60
  text "PER ORDER" at 13767.46,1599.76 h60
  text "XX MIL VIAS REQUIRE NON-CONDUCTIVE FILL AND PLANARIZE" at 11576.38,1394.82 h59
  text "XX MIL VIAS REQUIRE CONDUCTIVE FILL AND PLANARIZE" at 11584.38,1290.84 h60
  text "OUTER XX MIL TRACES REQUIRE 50 OHM SINGLE-ENDED IMPEDANCE" at 11583.39,1127.46 h58
  text "LAYER 2 & 3 (INNER LAYERS) XX MIL WIDE, XX MIL SPACE / TRACES REQUIRE 100 OHM DIFFERENTIAL IMPEDANCE" at 11575.39,891.74 h60
  text ".Layer_Name" at 577,-858.49 h60
M11 Gerber Information:
  lines w10: -292,-930.17 6308,-930.17 ; -292,-726.83 6310,-726.83 ; -292,-523.5 -292,-1133.5 3713,-1133.5 6310,-1133.5 6310,-523.5 -291.5,-523.5 -291.5,-1133.5 1284,-1133.5 ; 2173,-1133.5 2173,-523.5 ; 3440,-726.83 3440,-523.5 ; 4280,-726.83 4280,-523.5 ; 4902,-1140 4902,-937.17
  text "ALL ARTWORK VIEWED FROM TOP SIDE" at -228.5,-655.67 h60
  text "BOARD #:" at 2248,-655.67 h60
  text ".PRJ_Number" at 2793.5,-655.67 h60
  text "REV:" at 3638,-655.67 h60
  text ".PCB_Rev" at 3929.5,-655.67 h60
  text "SVN REV:" at 4476,-655.67 h60
  text ".VersionControl_RevNumber" at 4982,-655.67 h60
  text "LAYER NAME =" at -228.5,-858.49 h60
  text "TID #:" at 2248,-859 h60
  text ".TID" at 2793.5,-859 h60
  text "PLOT NAME =" at -228.5,-1064.34 h60
  text ".plot_File_Name" at 577,-1064.34 h60
  text "GENERATED    :" at 2250,-1064.34 h60
  text ".Print_Date" at 3119.5,-1064.34 h60
  text ".Print_Time" at 3848.5,-1064.34 h60
  text "TEXAS INSTRUMENTS" at 5113,-1064.34 h60
M12 Stackup:
  drawing of 295 lines, arcs and shapes, not listed
  text "Layer" at 9782.5,7847.5 h60
  text "Name" at 10192.41,7847.5 h60
  text "Material" at 11122.16,7847.5 h60
  text "Thickness" at 11981.92,7847.5 h60
  text "Constant" at 12631.76,7847.5 h60
  text "Board Layer Stack" at 13201.62,7847.5 h60
  text "1" at 9782.5,7727.5 h60
  text "Top Overlay" at 10192.41,7727.5 h60
  text "2" at 9782.5,7607.5 h60
  text "Top Solder" at 10192.41,7607.5 h60
  text "Solder Resist" at 11122.16,7607.5 h60
  text "0.40mil" at 11981.92,7607.5 h60
  text "3.5" at 12631.76,7607.5 h60
  text "3" at 9782.5,7487.5 h60
  text "L01_TOP" at 10192.41,7487.5 h60
  text "Copper" at 11122.16,7487.5 h60
  text "1.40mil" at 11981.92,7487.5 h60
  text "4" at 9782.5,7367.5 h60
  text "Dielectric 2" at 10192.41,7367.5 h60
  text "10.00mil" at 11981.92,7367.5 h60
  text "4.2" at 12631.76,7367.5 h60
  text "5" at 9782.5,7247.5 h60
  text "L02_GND" at 10192.41,7247.5 h60
  text "Copper" at 11122.16,7247.5 h60
  text "1.42mil" at 11981.92,7247.5 h60
  text "6" at 9782.5,7127.5 h60
  text "Dielectric1" at 10192.41,7127.5 h60
  text "FR-4" at 11122.16,7127.5 h60
  text "36.60mil" at 11981.92,7127.5 h60
  text "4.8" at 12631.76,7127.5 h60
  text "7" at 9782.5,7007.5 h60
  text "L03_PWR" at 10192.41,7007.5 h60
  text "Copper" at 11122.16,7007.5 h60
  text "1.42mil" at 11981.92,7007.5 h60
  text "8" at 9782.5,6887.5 h60
  text "Dielectric 3" at 10192.41,6887.5 h60
  text "10.00mil" at 11981.92,6887.5 h60
  text "4.2" at 12631.76,6887.5 h60
  text "9" at 9782.5,6767.5 h60
  text "L04_BOT" at 10192.41,6767.5 h60
  text "Copper" at 11122.16,6767.5 h60
  text "1.40mil" at 11981.92,6767.5 h60
  text "10" at 9782.5,6647.5 h60
  text "Bottom Solder" at 10192.41,6647.5 h60
  text "Solder Resist" at 11122.16,6647.5 h60
  text "0.40mil" at 11981.92,6647.5 h60
  text "3.5" at 12631.76,6647.5 h60
  text "11" at 9782.5,6527.5 h60
  text "Bottom Overlay" at 10192.41,6527.5 h60
  text ".Layer_Name" at 577,-858.49 h60
M13 Component Bodies Top:
  text ".Layer_Name" at 577,-858.49 h60
M14 Component Bodies Bottom:
  text ".Layer_Name" at 577,-858.49 h60
M15 Courtyards Top:
  text ".Layer_Name" at 577,-858.49 h60
M16 Courtyards Bottom:
  text ".Layer_Name" at 577,-858.49 h60
Drill Drawing:
  circle w10: c4469.12,963.33 r33.33
  lines w10: 4435.79,1080 4502.46,1080 4502.46,1146.67 4435.79,1146.67 4435.79,1080 ; 4435.79,1246.67 4452.46,1246.67 4452.46,1230 4485.79,1230 4485.79,1246.67 4502.46,1246.67 4502.46,1280 4485.79,1280 4485.79,1296.67 4452.46,1296.67 4452.46,1280 4435.79,1280 4435.79,1246.67 ; 4435.79,1446.67 4502.46,1446.67 4469.12,1380 4435.79,1446.67 ; 4435.79,1546.67 4452.46,1546.67 4469.12,1530 4485.79,1546.67 4502.46,1546.67 4485.79,1563.33 4502.46,1580 4485.79,1580 4469.12,1596.67 4452.46,1580 4435.79,1580 4452.46,1563.33 4435.79,1546.67 ; 4435.79,1680 4469.12,1696.67 4502.46,1680 4485.79,1713.33 4502.46,1746.67 4469.12,1730 4435.79,1746.67 4452.46,1713.33 4435.79,1680
  lines w12: 4376,885 7461.19,885 ; 4376,1785 7461.19,1785 ; 4926.88,735 4926.88,1935 ; 5564.71,735 5564.71,1935 ; 6910.31,735 6910.31,1935 ; 4376,735 7461.19,735 7461.19,1935 4376,1935 4376,735
  text "Symbol" at 4466,1830 h72
  text "Quantity" at 4971.88,1830 h72
  text "Finished Hole Size" at 5609.71,1830 h72
  text "Plated" at 6955.31,1830 h72
  text "170" at 4971.88,1680 h60
  text "12.00mil (0.305mm)" at 5609.71,1680 h60
  text "PTH" at 6955.31,1680 h60
  text "12" at 4971.88,1530 h60
  text "18.00mil (0.457mm)" at 5609.71,1530 h60
  text "PTH" at 6955.31,1530 h60
  text "22" at 4971.88,1380 h60
  text "40.00mil (1.016mm)" at 5609.71,1380 h60
  text "PTH" at 6955.31,1380 h60
  text "9" at 4971.88,1230 h60
  text "55.12mil (1.400mm)" at 5609.71,1230 h60
  text "PTH" at 6955.31,1230 h60
  text "9" at 4971.88,1080 h60
  text "63.00mil (1.600mm)" at 5609.71,1080 h60
  text "PTH" at 6955.31,1080 h60
  text "4" at 4971.88,930 h60
  text "125.98mil (3.200mm)" at 5609.71,930 h60
  text "PTH" at 6955.31,930 h60
  text "226 Total" at 4971.88,780 h60
  text ".Layer_Name" at 577,-858.49 h60
M17 Embedded Cavity:
  text ".Layer_Name" at 577,-858.49 h60
M18 Embedded Assembly:
  text ".Layer_Name" at 577,-858.49 h60
M19 Embedded Keepout:
  text ".Layer_Name" at 577,-858.49 h60

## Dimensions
0,-400 to 1000,-400 on M2 Board Dimensions
3760,0 to 3760,2600 on M2 Board Dimensions
0,2600 to 3760,2600 on M2 Board Dimensions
